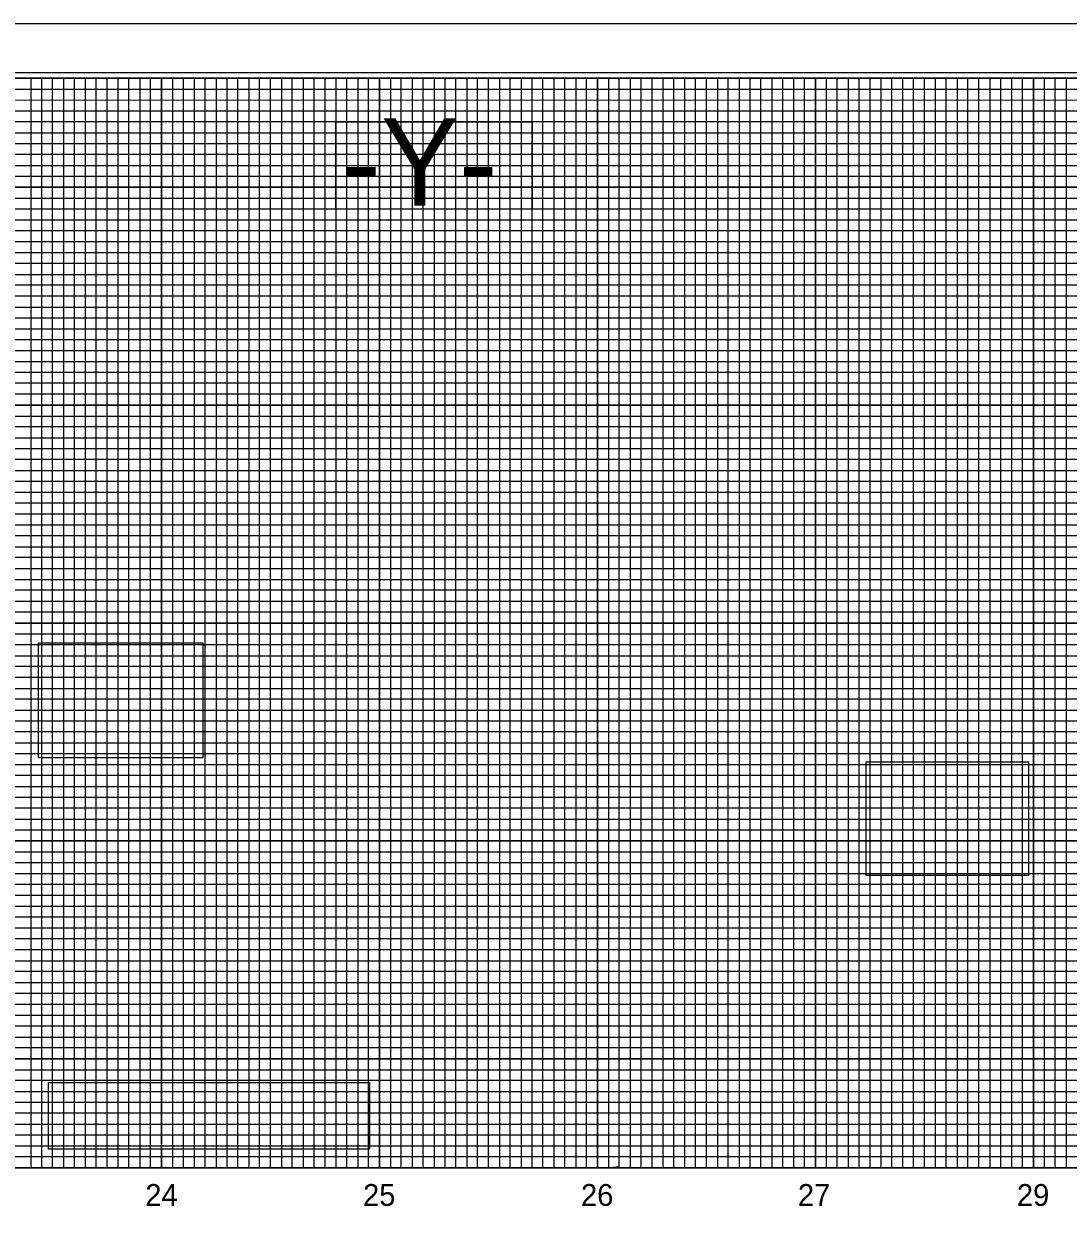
# Model space of a CAD drawing. Extents: x 1779926 to 1781610, y 620464 to 621564.
# Drawn here: x 1780680 to 1781159, y 621018 to 621564 of the extents above; entities that cross this region are included whole.
import ezdxf

# ---------------------------------------------------------------- set-up
doc = ezdxf.new("R2010")
doc.units = 0
for name, color, linetype in [('Exist Vertical Profile Horizontal Axis Label Major', 7, 'Continuous'), ('Exist Vertical Profile Vertical Axis Label', 7, 'Continuous'), ('Prop Grid Mask', 7, 'Continuous'), ('Scratch_Level_0', 7, 'Continuous'), ('Sheet Cutting Line CELL', 7, 'Continuous'), ('Sheet DOT Grid CELL', 7, 'Continuous'), ('Sheet Layout Profile Border Port 1', 7, 'Continuous'), ('Sheet Plot Border Inside CELL', 7, 'Continuous'), ('Sheet Plot Border Outside CELL', 7, 'Continuous'), ('Sheet Profile CELL', 7, 'Continuous'), ('Sheet Profile Grid Major CELL', 7, 'Continuous'), ('Sheet Profile Grid Middle CELL', 7, 'Continuous'), ('Sheet Profile Grid Minor CELL', 7, 'Continuous')]:
    doc.layers.add(name, color=color, linetype=linetype)

msp = doc.modelspace()

# ---------------------------------------------------------------- linework, layer by layer
at = {"layer": 'Prop Grid Mask'}
for points in [[(1780822.96, 621519.19), (1780912.96, 621519.19), (1780912.96, 621479.19), (1780822.96, 621479.19)], [(1780686.56, 621280.06), (1780761.9, 621280.06), (1780761.9, 621227.26), (1780686.56, 621227.26)], [(1781066.21, 621225.47), (1781140.77, 621225.47), (1781140.77, 621173.37), (1781066.21, 621173.37)], [(1780691.1, 621078.26), (1780838.4, 621078.26), (1780838.4, 621047.65), (1780691.1, 621047.65)]]:
    msp.add_lwpolyline(points, close=True, dxfattribs=at)
at = {"layer": 'Scratch_Level_0'}
msp.add_lwpolyline([(1780192.96, 621039.19), (1780192.96, 621539.19), (1781392.96, 621539.19), (1781392.96, 621314.19), (1781542.96, 621314.19), (1781542.96, 621039.19)], close=True, dxfattribs=at)
at = {"layer": 'Sheet Cutting Line CELL'}
msp.add_line((1781609.96, 621564.19), (1779925.96, 621564.19), dxfattribs=at)
at = {"layer": 'Sheet DOT Grid CELL'}
for p, q in [((1780692.96, 621039.19), (1780692.96, 621539.19)), ((1780742.96, 621039.19), (1780742.96, 621539.19)), ((1780792.96, 621039.19), (1780792.96, 621539.19)), ((1780842.96, 621039.19), (1780842.96, 621539.19)), ((1780892.96, 621039.19), (1780892.96, 621539.19)), ((1780942.96, 621039.19), (1780942.96, 621539.19)), ((1780992.96, 621039.19), (1780992.96, 621539.19)), ((1781042.96, 621039.19), (1781042.96, 621539.19)), ((1781092.96, 621039.19), (1781092.96, 621539.19)), ((1781142.96, 621039.19), (1781142.96, 621539.19)), ((1781392.91, 621489.19), (1780092.96, 621489.19)), ((1781392.91, 621439.19), (1780092.96, 621439.19)), ((1781392.96, 621389.19), (1780092.96, 621389.19)), ((1781392.91, 621339.19), (1780092.96, 621339.19)), ((1781592.96, 621289.19), (1780092.96, 621289.19)), ((1781592.96, 621239.19), (1780092.96, 621239.19)), ((1781592.96, 621189.19), (1780092.96, 621189.19)), ((1781592.96, 621139.19), (1780092.96, 621139.19)), ((1781592.96, 621089.19), (1780092.96, 621089.19))]:
    msp.add_line(p, q, dxfattribs=at)
at = {"layer": 'Sheet Layout Profile Border Port 1'}
msp.add_lwpolyline([(1781392.96, 621539.19), (1781392.9, 621314.19), (1781532.96, 621314.19), (1781532.96, 621039.19), (1780182.96, 621039.19), (1780182.96, 621539.19)], close=True, dxfattribs=at)
msp.add_lwpolyline([(1780142.96, 621378.14), (1780142.96, 621039.19), (1781542.96, 621039.19), (1781542.96, 621314.19)], dxfattribs=at)
at = {"layer": 'Sheet Plot Border Inside CELL'}
msp.add_lwpolyline([(1779938.96, 620486.64), (1781605.46, 620486.64), (1781605.46, 621541.74), (1779938.96, 621541.74)], close=True, dxfattribs=at)
at = {"layer": 'Sheet Plot Border Outside CELL'}
msp.add_lwpolyline([(1779925.96, 620464.19), (1781609.96, 620464.19), (1781609.96, 621564.19), (1779925.96, 621564.19)], close=True, dxfattribs=at)
at = {"layer": 'Sheet Profile CELL'}
msp.add_line((1780092.96, 621039.19), (1781592.96, 621039.19), dxfattribs=at)
msp.add_lwpolyline([(1781592.96, 621539.19), (1780092.96, 621539.19), (1780092.96, 620489.19), (1781592.96, 620489.19)], close=True, dxfattribs=at)
at = {"layer": 'Sheet Profile Grid Major CELL'}
for points in [[(1780642.96, 621039.19), (1780692.96, 621039.19), (1780692.96, 621539.19), (1780742.96, 621539.19), (1780742.96, 621039.19), (1780792.96, 621039.19), (1780792.96, 621539.19), (1780842.96, 621539.19), (1780842.96, 621039.19), (1780892.96, 621039.19), (1780892.96, 621539.19), (1780942.96, 621539.19), (1780942.96, 621039.19), (1780992.96, 621039.19), (1780992.96, 621539.19), (1781042.96, 621539.19), (1781042.96, 621039.19), (1781092.96, 621039.19), (1781092.96, 621539.19), (1781142.96, 621539.19), (1781142.96, 621039.19), (1781192.96, 621039.19)], [(1780092.96, 621489.19), (1781392.96, 621489.19)], [(1781392.96, 621439.19), (1780092.96, 621439.19), (1780092.96, 621389.19), (1781392.96, 621389.19)], [(1781392.91, 621339.19), (1780092.96, 621339.19), (1780092.96, 621289.19), (1781592.96, 621289.19)], [(1781592.96, 621239.19), (1780092.96, 621239.19), (1780092.96, 621189.19), (1781592.96, 621189.19)], [(1781592.96, 621139.19), (1780092.96, 621139.19), (1780092.96, 621139.19), (1780092.96, 621089.19), (1781592.96, 621089.19)]]:
    msp.add_lwpolyline(points, dxfattribs=at)
at = {"layer": 'Sheet Profile Grid Middle CELL'}
msp.add_line((1780092.96, 621514.19), (1781392.91, 621514.19), dxfattribs=at)
for points in [[(1780667.96, 621039.19), (1780717.96, 621039.19), (1780717.96, 621039.19), (1780717.96, 621539.19), (1780767.96, 621539.19), (1780767.96, 621039.19), (1780817.96, 621039.19), (1780817.96, 621539.19), (1780867.96, 621539.19), (1780867.96, 621039.19), (1780917.96, 621039.19), (1780917.96, 621539.19), (1780967.96, 621539.19), (1780967.96, 621039.19), (1781017.96, 621039.19), (1781017.96, 621539.19), (1781067.96, 621539.19), (1781067.96, 621039.19), (1781117.96, 621039.19), (1781117.96, 621539.19), (1781167.96, 621539.19)], [(1781392.96, 621464.19), (1780092.96, 621464.19), (1780092.96, 621414.19), (1781392.96, 621414.19)], [(1781392.91, 621364.19), (1780092.96, 621364.19), (1780092.96, 621314.19), (1781417.96, 621314.19)], [(1781592.96, 621264.19), (1780092.96, 621264.19), (1780092.96, 621214.19), (1781592.96, 621214.19)], [(1781592.96, 621164.19), (1780092.96, 621164.19), (1780092.96, 621114.19), (1781592.96, 621114.19)], [(1781592.96, 621064.19), (1780092.96, 621064.19)]]:
    msp.add_lwpolyline(points, dxfattribs=at)
at = {"layer": 'Sheet Profile Grid Minor CELL'}
for p, q in [((1780142.96, 621534.19), (1781392.96, 621534.19)), ((1781392.96, 621529.19), (1780142.96, 621528.84)), ((1780142.96, 621524.19), (1781392.96, 621524.19)), ((1781392.91, 621404.19), (1780142.96, 621404.19)), ((1781392.96, 621399.19), (1780142.96, 621399.19)), ((1781392.96, 621394.19), (1780142.96, 621394.19)), ((1780142.96, 621384.19), (1781392.96, 621384.19)), ((1781392.96, 621379.19), (1780142.96, 621379.19)), ((1780142.96, 621374.19), (1781392.96, 621374.19)), ((1781392.96, 621354.19), (1780142.96, 621354.19)), ((1780142.96, 621349.19), (1781392.96, 621349.19)), ((1781392.91, 621329.19), (1780142.96, 621329.19)), ((1780142.96, 621324.19), (1781392.91, 621324.19)), ((1781542.96, 621304.19), (1780142.96, 621304.19)), ((1780142.96, 621299.19), (1781542.96, 621299.19)), ((1781542.96, 621294.19), (1780142.96, 621294.19)), ((1780142.96, 621284.19), (1781542.96, 621284.19)), ((1781542.96, 621279.19), (1780142.96, 621279.19)), ((1780142.96, 621274.19), (1781542.96, 621274.19)), ((1781542.96, 621269.19), (1780142.96, 621269.19)), ((1780142.96, 621259.19), (1781542.96, 621259.19)), ((1781542.96, 621254.19), (1780142.96, 621254.19)), ((1780142.96, 621249.19), (1781542.96, 621249.19)), ((1781542.96, 621244.19), (1780142.96, 621244.19)), ((1780142.96, 621234.19), (1781542.96, 621234.19)), ((1781542.96, 621229.19), (1780142.96, 621229.19)), ((1780142.96, 621224.19), (1781542.96, 621224.19)), ((1781542.96, 621219.19), (1780142.96, 621219.19)), ((1780142.96, 621209.19), (1781542.96, 621209.19)), ((1781542.96, 621204.19), (1780142.96, 621204.19)), ((1780142.96, 621199.19), (1781542.96, 621199.19)), ((1781542.96, 621194.19), (1780142.96, 621194.19)), ((1780142.96, 621184.19), (1781542.96, 621184.19)), ((1781542.96, 621179.19), (1780142.96, 621179.19)), ((1780142.96, 621174.19), (1781542.96, 621174.19)), ((1781542.96, 621169.19), (1780142.96, 621169.19)), ((1780142.96, 621159.19), (1781542.96, 621159.19)), ((1781542.96, 621154.19), (1780142.96, 621154.19)), ((1781542.96, 621149.19), (1780142.96, 621149.19)), ((1781542.96, 621144.19), (1780142.96, 621144.19)), ((1780142.96, 621134.19), (1781542.96, 621134.19)), ((1781542.96, 621129.19), (1780142.96, 621129.19)), ((1780142.96, 621124.19), (1781542.96, 621124.19)), ((1781542.96, 621119.19), (1780142.96, 621119.19)), ((1780142.96, 621109.19), (1781542.96, 621109.19)), ((1781542.96, 621104.19), (1780142.96, 621104.19)), ((1780142.96, 621099.19), (1781542.96, 621099.19)), ((1781542.96, 621094.19), (1780142.96, 621094.19)), ((1780142.96, 621084.19), (1781542.96, 621084.19)), ((1781542.96, 621079.19), (1780142.96, 621079.19)), ((1780142.96, 621074.19), (1781542.96, 621074.19)), ((1781542.96, 621069.19), (1780142.96, 621069.19)), ((1780142.96, 621059.19), (1781542.96, 621059.19)), ((1781542.96, 621054.19), (1780142.96, 621054.19)), ((1780142.96, 621049.19), (1781542.96, 621049.19))]:
    msp.add_line(p, q, dxfattribs=at)
for points in [[(1780677.96, 621539.19), (1780682.96, 621539.19), (1780682.96, 621039.19), (1780687.96, 621039.19), (1780687.96, 621539.19), (1780697.96, 621539.19), (1780697.96, 621039.19), (1780702.96, 621039.19), (1780702.96, 621539.19), (1780707.96, 621539.19), (1780707.96, 621039.19), (1780712.96, 621039.19), (1780712.96, 621539.19), (1780722.96, 621539.19), (1780722.96, 621039.19), (1780727.96, 621039.19), (1780727.96, 621539.19), (1780732.96, 621539.19), (1780732.96, 621039.19), (1780737.96, 621039.19), (1780737.96, 621539.19), (1780747.96, 621539.19), (1780747.96, 621039.19), (1780752.96, 621039.19), (1780752.96, 621539.19), (1780757.96, 621539.19), (1780757.96, 621039.19), (1780762.96, 621039.19), (1780762.96, 621539.19), (1780772.96, 621539.19), (1780772.96, 621039.19), (1780777.96, 621039.19), (1780777.96, 621539.19), (1780782.96, 621539.19), (1780782.96, 621039.19), (1780787.96, 621039.19), (1780787.96, 621539.19), (1780797.96, 621539.19), (1780797.96, 621039.19), (1780797.96, 621039.19), (1780802.96, 621039.19), (1780802.96, 621539.19), (1780807.96, 621539.19), (1780807.96, 621039.19), (1780812.96, 621039.19), (1780812.96, 621539.19), (1780822.96, 621539.19), (1780822.96, 621039.19), (1780827.96, 621039.19), (1780827.96, 621539.19), (1780832.96, 621539.19), (1780832.96, 621039.19), (1780837.96, 621039.19), (1780837.96, 621539.19), (1780847.96, 621539.19), (1780847.96, 621039.19), (1780852.96, 621039.19), (1780852.96, 621539.19), (1780857.96, 621539.19), (1780857.96, 621039.19), (1780862.96, 621039.19), (1780862.96, 621539.19), (1780872.96, 621539.19), (1780872.96, 621039.19), (1780877.96, 621039.19), (1780877.96, 621539.19), (1780882.96, 621539.19), (1780882.96, 621039.19), (1780887.96, 621039.19), (1780887.96, 621539.19), (1780897.96, 621539.19), (1780897.96, 621039.19), (1780902.96, 621039.19), (1780902.96, 621539.19), (1780907.96, 621539.19), (1780907.96, 621039.19), (1780912.96, 621039.19), (1780912.96, 621539.19), (1780922.96, 621539.19), (1780922.96, 621039.19), (1780927.96, 621039.19), (1780927.96, 621539.19), (1780932.96, 621539.19), (1780932.96, 621039.19), (1780937.96, 621039.19), (1780937.96, 621539.19), (1780947.96, 621539.19), (1780947.96, 621039.19), (1780952.66, 621039.74), (1780952.96, 621039.19), (1780952.96, 621539.19), (1780957.96, 621539.19), (1780957.96, 621039.19), (1780962.96, 621039.19), (1780962.96, 621539.19), (1780972.96, 621539.19), (1780972.96, 621039.19), (1780977.96, 621039.19)], [(1780977.96, 621039.19), (1780977.96, 621539.19), (1780982.96, 621539.19), (1780982.96, 621039.19), (1780987.96, 621039.19), (1780987.96, 621539.19), (1780997.96, 621539.19), (1780997.96, 621039.19), (1781002.96, 621039.19), (1781002.96, 621539.19), (1781007.96, 621539.19), (1781007.96, 621039.19), (1781012.96, 621039.19), (1781012.96, 621539.19), (1781022.96, 621539.19), (1781022.96, 621039.19), (1781027.96, 621039.19), (1781027.96, 621539.19), (1781032.96, 621539.19), (1781032.96, 621039.19), (1781037.96, 621039.19), (1781037.96, 621539.19), (1781047.96, 621539.19), (1781047.96, 621039.19), (1781052.96, 621039.19), (1781052.96, 621539.19), (1781057.96, 621539.19), (1781057.96, 621039.19), (1781062.96, 621039.19), (1781062.96, 621539.19), (1781072.96, 621539.19), (1781072.96, 621039.19), (1781077.96, 621039.19), (1781077.96, 621539.19), (1781082.96, 621539.19), (1781082.96, 621039.19), (1781087.96, 621039.19), (1781087.96, 621539.19), (1781097.96, 621539.19), (1781097.96, 621039.19), (1781102.96, 621039.19), (1781102.96, 621539.19), (1781107.96, 621539.19), (1781107.96, 621039.19), (1781112.96, 621039.19), (1781112.96, 621539.19), (1781122.96, 621539.19), (1781122.96, 621039.19), (1781127.96, 621039.19), (1781127.96, 621539.19), (1781132.96, 621539.19), (1781132.96, 621039.19), (1781137.96, 621039.19), (1781137.96, 621539.19), (1781147.96, 621539.19), (1781147.96, 621039.19), (1781152.96, 621039.19), (1781152.96, 621539.19), (1781157.96, 621539.19), (1781157.96, 621039.19), (1781162.96, 621039.19)], [(1781392.96, 621519.19), (1780142.96, 621519.19), (1780142.96, 621509.19), (1781392.96, 621509.19)], [(1781392.91, 621504.19), (1780142.96, 621504.19), (1780142.96, 621499.19), (1781392.96, 621499.19)], [(1781392.96, 621494.19), (1780142.96, 621494.19), (1780142.96, 621484.19), (1781392.96, 621484.19)], [(1781392.96, 621479.19), (1780142.96, 621479.19), (1780142.96, 621474.19), (1781392.96, 621474.19)], [(1781392.96, 621469.19), (1780142.96, 621469.19), (1780142.96, 621459.19), (1781392.96, 621459.19)], [(1781392.96, 621454.19), (1780142.96, 621454.19), (1780142.96, 621449.19), (1781392.96, 621449.19)], [(1781392.96, 621444.19), (1780142.96, 621444.19), (1780142.96, 621434.19), (1781392.96, 621434.19)], [(1781392.96, 621429.09), (1780143.06, 621429.09), (1780143.06, 621424.19), (1781392.96, 621424.19)], [(1781392.96, 621419.19), (1780142.96, 621419.19), (1780142.96, 621409.19), (1781392.96, 621409.19)], [(1781392.91, 621369.19), (1780142.96, 621369.19), (1780142.96, 621359.19), (1781392.91, 621359.19)], [(1781392.91, 621344.19), (1780142.96, 621344.19), (1780142.96, 621334.19), (1781392.91, 621334.19)], [(1781392.91, 621319.19), (1780142.96, 621319.19), (1780142.96, 621309.19), (1781542.96, 621309.19)], [(1781542.96, 621044.19), (1780142.96, 621044.19)]]:
    msp.add_lwpolyline(points, dxfattribs=at)

# ---------------------------------------------------------------- texts
at = {"layer": 'Exist Vertical Profile Horizontal Axis Label Major'}
for s, p in [('24', (1780735.49, 621021.69)), ('25', (1780835.39, 621021.69)), ('26', (1780935.38, 621021.69)), ('27', (1781034.91, 621021.69)), ('29', (1781135.39, 621021.69))]:
    msp.add_text(s, height=10, dxfattribs=at).set_placement(p)
at = {"layer": 'Exist Vertical Profile Vertical Axis Label'}
msp.add_text('-Y-', height=40, dxfattribs=at).set_placement((1780825.81, 621480.78))

doc.saveas('drawing.dxf')
